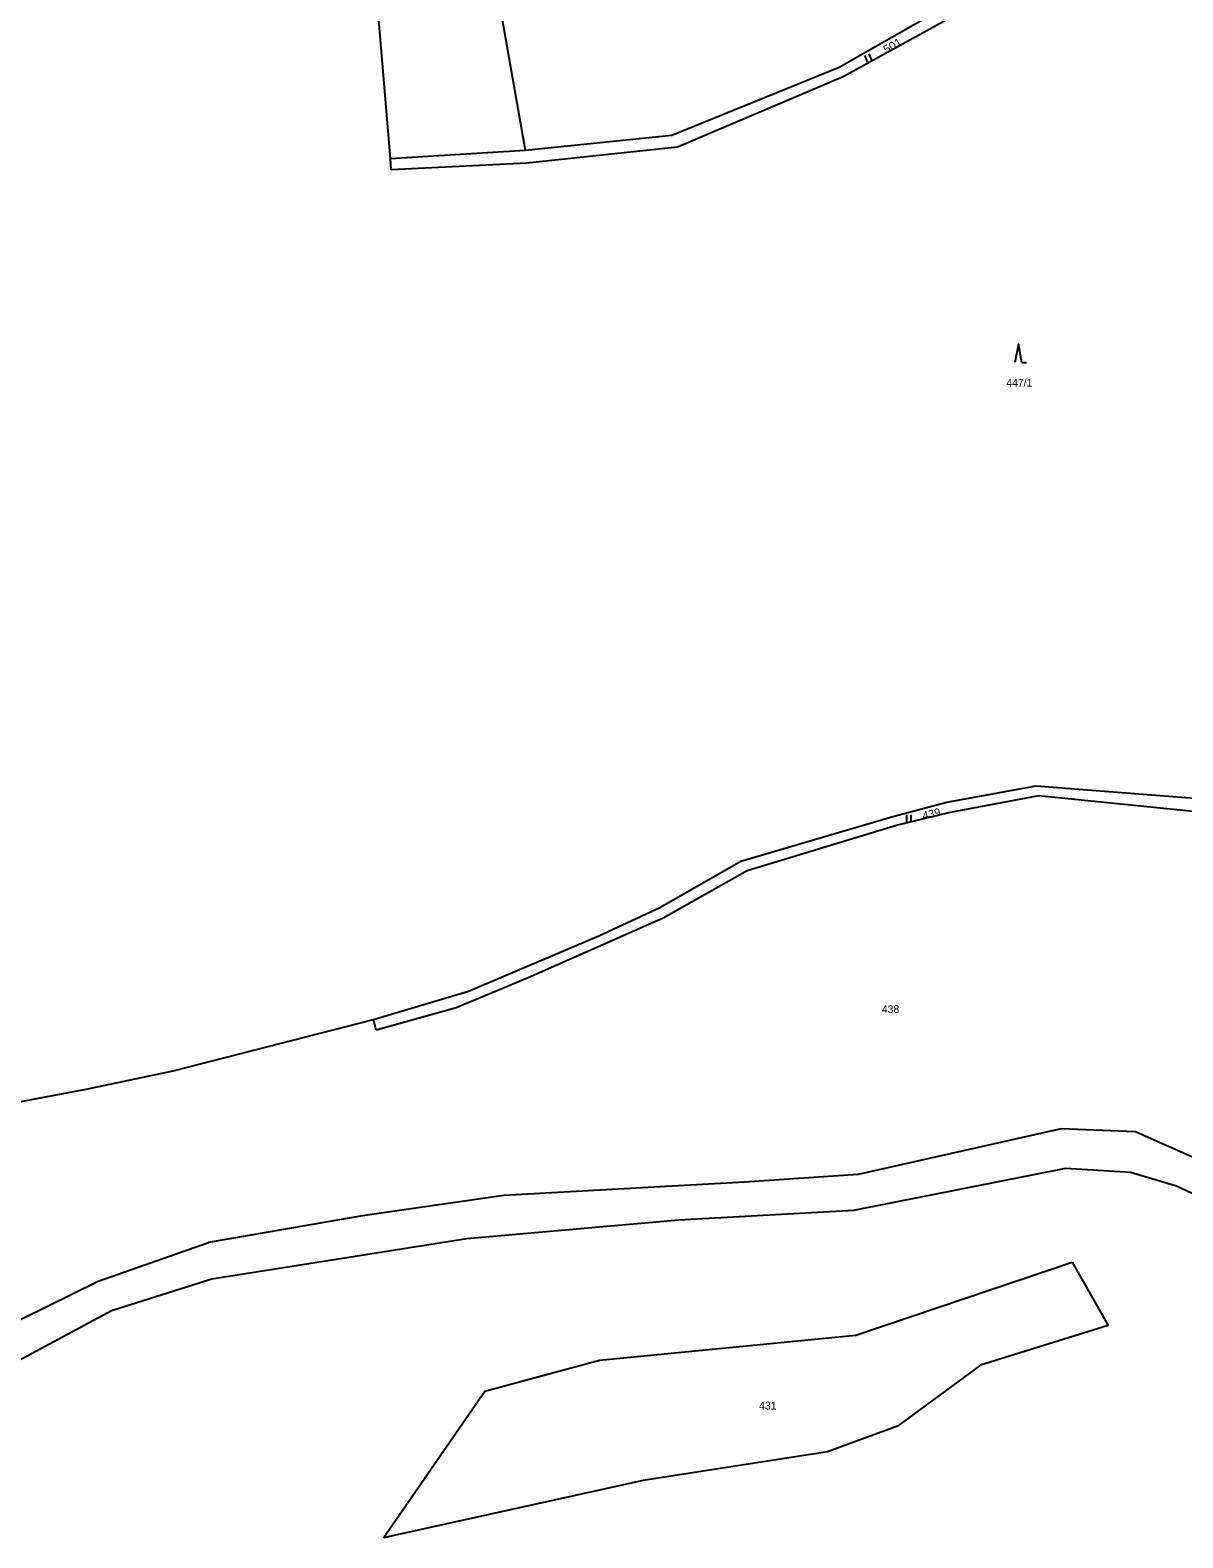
# Model space of a CAD drawing. Extents: x -744132 to -742433, y -984679 to -982287.
# Drawn here: x -743670 to -743418.3, y -984036.4 to -983707.4 of the extents above; entities that cross this region are included whole.
import ezdxf

# ---------------------------------------------------------------- set-up
doc = ezdxf.new("R2010")
doc.units = 0
doc.header["$LTSCALE"] = 0.68
doc.layers.add('1', color=7, linetype='Continuous', lineweight=25)
doc.layers.add('3', color=7, linetype='Continuous', lineweight=25)
doc.layers.add('2', color=7, linetype='Continuous')

msp = doc.modelspace()

# ---------------------------------------------------------------- linework, layer by layer
at = {"layer": '1'}
for p, q in [((-743493.35, -983715.46), (-743442.59, -983686.58)), ((-743441.65, -983689.59), (-743492.49, -983717.63)), ((-743591.31, -983735.46), (-743594.23, -983700.82)), ((-743567.11, -983704.28), (-743561.89, -983733.64)), ((-743529.89, -983730.32), (-743493.35, -983715.46)), ((-743492.49, -983717.63), (-743528.68, -983732.95)), ((-743561.89, -983733.64), (-743529.89, -983730.32)), ((-743591.31, -983735.46), (-743561.89, -983733.64)), ((-743591.2, -983737.89), (-743591.31, -983735.46)), ((-743528.68, -983732.95), (-743561.52, -983736.42)), ((-743561.52, -983736.42), (-743591.2, -983737.89)), ((-743469.83, -983875.85), (-743450.34, -983872.31)), ((-743450.34, -983872.31), (-743413.04, -983875.25)), ((-743481.61, -983878.97), (-743469.83, -983875.85)), ((-743449.87, -983874.5), (-743469.46, -983878.18)), ((-743415.34, -983877.96), (-743449.87, -983874.5)), ((-743514.84, -983888.73), (-743481.61, -983878.97)), ((-743469.46, -983878.18), (-743480.65, -983880.86)), ((-743480.65, -983880.86), (-743513.47, -983890.86)), ((-743532.52, -983898.89), (-743514.84, -983888.73)), ((-743513.47, -983890.86), (-743531.79, -983901.16)), ((-743545.86, -983905.02), (-743532.52, -983898.89)), ((-743531.79, -983901.16), (-743561.27, -983914.22)), ((-743574.28, -983917.14), (-743545.86, -983905.02)), ((-743561.27, -983914.22), (-743576.99, -983920.74)), ((-743595.04, -983923.26), (-743574.28, -983917.14)), ((-743576.99, -983920.74), (-743594.42, -983925.65)), ((-743638.79, -983934.47), (-743595.04, -983923.26)), ((-743594.42, -983925.65), (-743595.04, -983923.26)), ((-743657.74, -983938.48), (-743638.79, -983934.47)), ((-743712.18, -983948.85), (-743657.74, -983938.48)), ((-743444.91, -983947.12), (-743489.19, -983957.1)), ((-743428.65, -983947.79), (-743444.91, -983947.12)), ((-743408.45, -983956.84), (-743428.65, -983947.79)), ((-743490.19, -983964.93), (-743443.89, -983955.71)), ((-743443.89, -983955.71), (-743429.74, -983956.64)), ((-743514.03, -983958.77), (-743566.58, -983961.69)), ((-743489.19, -983957.1), (-743514.03, -983958.77)), ((-743429.74, -983956.64), (-743419.68, -983959.57)), ((-743566.58, -983961.69), (-743597.41, -983966.16)), ((-743419.68, -983959.57), (-743385.24, -983975.95)), ((-743528.35, -983966.98), (-743490.19, -983964.93)), ((-743597.41, -983966.16), (-743631.05, -983971.96)), ((-743574.63, -983971.07), (-743528.35, -983966.98)), ((-743655.16, -983980.38), (-743631.05, -983971.96)), ((-743630.3, -983979.87), (-743574.63, -983971.07)), ((-743489.74, -983992.21), (-743442.46, -983976.22)), ((-743442.46, -983976.22), (-743434.65, -983990.1)), ((-743682.75, -983994), (-743655.16, -983980.38)), ((-743652.22, -983986.81), (-743630.3, -983979.87)), ((-743685.87, -984004.83), (-743652.22, -983986.81)), ((-743545.65, -983997.64), (-743489.74, -983992.21)), ((-743434.65, -983990.1), (-743462.51, -983998.72)), ((-743570.7, -984004.37), (-743545.65, -983997.64)), ((-743462.51, -983998.72), (-743480.6, -984012)), ((-743592.87, -984036.4), (-743570.7, -984004.37)), ((-743480.6, -984012), (-743495.94, -984017.61)), ((-743495.94, -984017.61), (-743536.17, -984023.88)), ((-743536.17, -984023.88), (-743592.87, -984036.4))]:
    msp.add_line(p, q, dxfattribs=at)
at = {"layer": '3'}
for p, q in [((-743486.229, -983713.938), (-743486.815, -983712.558)), ((-743487.15, -983714.33), (-743487.736, -983712.949)), ((-743453.49, -983779.97), (-743452.494, -983779.97)), ((-743478.611, -983880.13), (-743478.611, -983878.63)), ((-743477.61, -983880.13), (-743477.61, -983878.63))]:
    msp.add_line(p, q, dxfattribs=at)
msp.add_lwpolyline([(-743453.49, -983779.97), (-743454.24, -983775.97), (-743454.99, -983779.97)], dxfattribs=at)

# ---------------------------------------------------------------- texts
at = {"layer": '2'}
for s, rotation, width, p in [('501', 30, 1.1, (-743483.117, -983712.558)), ('439', 14, 1.05, (-743474.947, -983879.712))]:
    msp.add_text(s, height=1.7, rotation=rotation, dxfattribs=dict(at, width=width)).set_placement(p)
for s, p in [('447/1', (-743456.87, -983785.205)), ('438', (-743484.03, -983921.885)), ('431', (-743510.84, -984008.395))]:
    msp.add_text(s, height=1.7, dxfattribs=at).set_placement(p)

doc.saveas('drawing.dxf')
